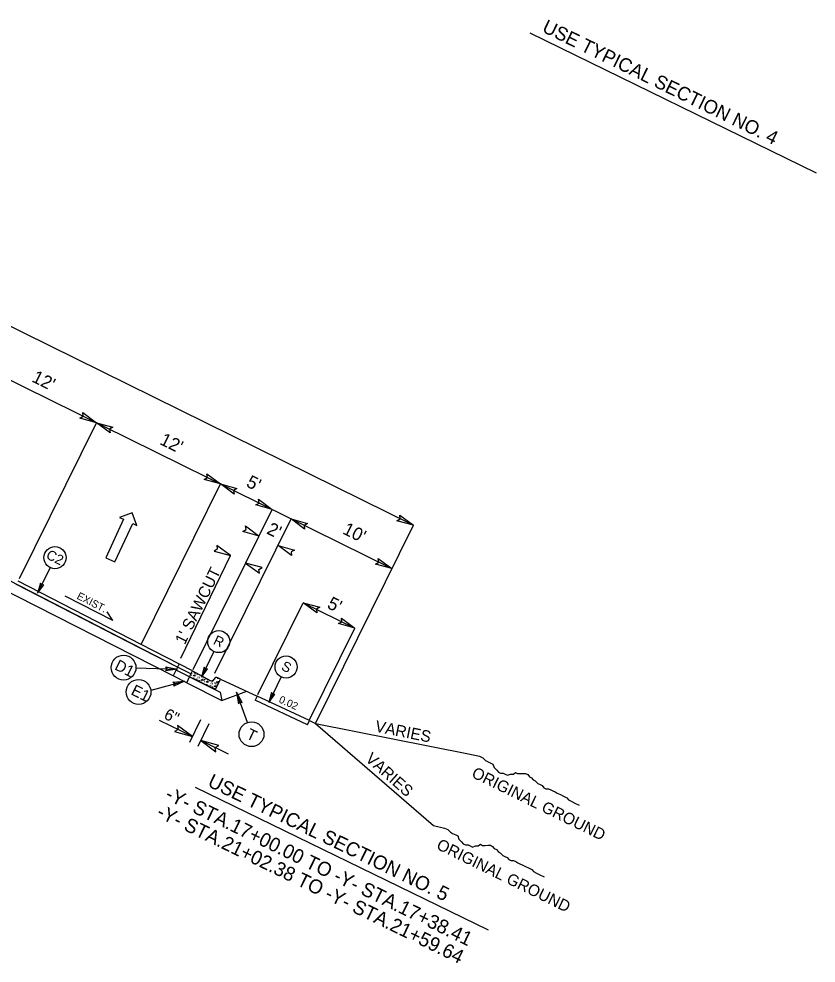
# Model space of a CAD drawing. Extents: x 1518247 to 1523638, y 635234 to 639927.
# Drawn here: x 1522712 to 1523403, y 635313 to 636132 of the extents above; entities that cross this region are included whole.
import ezdxf

# ---------------------------------------------------------------- set-up
doc = ezdxf.new("R2010")
doc.units = 0
for name, color, linetype in [('DTM TIN Hull White', 7, 'Continuous'), ('Prop Dimension', 7, 'Continuous'), ('Prop Lane Arrow CELL', 7, 'Continuous'), ('Prop Shade Light', 7, 'Continuous'), ('Sheet Typical CELL', 7, 'Continuous'), ('Typical Berm CELL', 7, 'Continuous'), ('Typical Berm Information CELL', 7, 'Continuous'), ('Typical Curb CELL', 7, 'Continuous'), ('Typical Hinge Slope Arterial CELL', 7, 'Continuous'), ('Typical Hinge Slope Interstate CELL', 7, 'Continuous'), ('Typical ID Circle CELL', 7, 'Continuous'), ('Typical Pavement Slope CELL', 7, 'Continuous'), ('Typical Pavement Slope Information CELL', 7, 'Continuous'), ('Typical Shoulder Slope CELL', 7, 'Continuous'), ('Typical Text ID Circle CELL', 7, 'Continuous'), ('Typical Text Label CELL', 7, 'Continuous')]:
    doc.layers.add(name, color=color, linetype=linetype)

# ---------------------------------------------------------------- blocks, each defined once
blk = doc.blocks.new('TERMINATOR')
at = {"layer": 'Prop Shade Light'}
blk.add_lwpolyline([(-0.469, 0.081), (0, 0), (-0.471, -0.083), (-0.411, 0)], close=True, dxfattribs=at)

msp = doc.modelspace()

# ---------------------------------------------------------------- linework, layer by layer
at = {"layer": 'DTM TIN Hull White'}
for p, q in [((1522849.5, 635569.87), (1522681, 635656.43)), ((1522845.72, 635562.41), (1522676.71, 635648.08))]:
    msp.add_line(p, q, dxfattribs=at)
at = {"layer": 'Prop Dimension'}
for p, q in [((1522165.11, 636131.96), (1523054.02, 635692.85)), ((1522146.52, 636094.32), (1523035.43, 635655.21)), ((1522712.52, 635646.73), (1522779.23, 635781.77)), ((1522818.32, 635590.03), (1522886.79, 635728.64)), ((1522863.14, 635567.89), (1522931.61, 635706.5)), ((1522881.84, 635564.61), (1522947.93, 635698.41)), ((1522969.34, 635521.41), (1523054.02, 635692.85)), ((1522852.4, 635577.73), (1522895.4, 635666.53)), ((1522919.28, 635546.14), (1522958.58, 635625.69)), ((1522958.58, 635625.69), (1523003.4, 635603.55)), ((1522964.11, 635524), (1523003.4, 635603.55)), ((1522862.49, 635509.62), (1522833.85, 635523.6)), ((1522869.55, 635524.08), (1522860.02, 635504.56)), ((1522876.72, 635520.58), (1522867.19, 635501.06)), ((1522893.66, 635494.4), (1522869.66, 635506.12))]:
    msp.add_line(p, q, dxfattribs=at)
at = {"layer": 'Prop Lane Arrow CELL'}
for p, q in [((1522810.29, 635703.64), (1522799.19, 635699.68)), ((1522799.19, 635699.68), (1522802.76, 635698.02)), ((1522814.19, 635692.71), (1522810.29, 635703.64)), ((1522802.76, 635698.02), (1522787.28, 635664.68)), ((1522795.13, 635661.03), (1522810.62, 635694.37)), ((1522810.62, 635694.37), (1522814.19, 635692.71)), ((1522787.28, 635664.68), (1522795.13, 635661.03))]:
    msp.add_line(p, q, dxfattribs=at)
at = {"layer": 'Prop Shade Light'}
for points in [[(1522730.7, 635642.56), (1522728.18, 635633.91), (1522733.51, 635641.24), (1522731.59, 635640.91)], [(1522839.52, 635570.17), (1522849.42, 635568.05), (1522839.32, 635566.68), (1522840.67, 635568.4)], [(1522872.74, 635569.78), (1522870.22, 635561.14), (1522875.55, 635568.47), (1522873.64, 635568.14)], [(1522845.48, 635556.76), (1522855.57, 635557.64), (1522846.31, 635553.37), (1522847.09, 635555.41)], [(1522905.71, 635539.26), (1522900.75, 635548.09), (1522902.44, 635538.04), (1522903.68, 635539.83)], [(1522931.14, 635547.74), (1522928.62, 635539.09), (1522933.95, 635546.42), (1522932.04, 635546.09)]]:
    msp.add_lwpolyline(points, close=True, dxfattribs=at)
at = {"layer": 'Sheet Typical CELL'}
for p, q in [((1522918.58, 635544.72), (1522916.88, 635541.1)), ((1522963.86, 635523.5), (1522918.58, 635544.72)), ((1522962.16, 635519.88), (1522916.88, 635541.1)), ((1522962.16, 635519.88), (1522963.86, 635523.5))]:
    msp.add_line(p, q, dxfattribs=at)
at = {"layer": 'Typical Berm CELL'}
for p, q in [((1522886.83, 635559.44), (1522918.58, 635544.72)), ((1522963.86, 635523.5), (1522969.16, 635521.05))]:
    msp.add_line(p, q, dxfattribs=at)
at = {"layer": 'Typical Curb CELL'}
for p, q in [((1522859.98, 635561.44), (1522862.54, 635566.68)), ((1522882.44, 635550.45), (1522859.98, 635561.44)), ((1522862.54, 635566.68), (1522877.95, 635558.33)), ((1522863.37, 635562.44), (1522864.68, 635563.14)), ((1522864.49, 635561.97), (1522863.37, 635562.44)), ((1522864.68, 635563.14), (1522864.49, 635561.97)), ((1522886.83, 635559.44), (1522884.49, 635560.58)), ((1522870.03, 635558.62), (1522871.09, 635559.38)), ((1522871.69, 635558.25), (1522870.03, 635558.62)), ((1522871.09, 635559.38), (1522871.69, 635558.25)), ((1522874.6, 635556.95), (1522875.89, 635557.65)), ((1522875.7, 635556.48), (1522874.6, 635556.95)), ((1522875.89, 635557.65), (1522875.7, 635556.48)), ((1522881.24, 635559.39), (1522881.29, 635559.48)), ((1522881.24, 635553.14), (1522882.31, 635553.89)), ((1522882.91, 635552.76), (1522881.24, 635553.14)), ((1522882.31, 635553.89), (1522882.91, 635552.76)), ((1522882.44, 635550.45), (1522886.83, 635559.44)), ((1522883.65, 635557.28), (1522883.4, 635556.39)), ((1522883.4, 635556.39), (1522884.84, 635556.2)), ((1522884.84, 635556.2), (1522883.65, 635557.28))]:
    msp.add_line(p, q, dxfattribs=at)
for centre in [(1522860.2, 635561.65), (1522861.5, 635562.86), (1522861.61, 635564.39), (1522861.99, 635560.52), (1522862.19, 635565.19), (1522862.54, 635564.63), (1522862.56, 635562.85), (1522863.73, 635560.43), (1522864.07, 635565.28), (1522864.56, 635564.09), (1522865.42, 635564.8), (1522866.29, 635562.55), (1522866.48, 635563.59), (1522867.25, 635561.13), (1522868.26, 635562.54), (1522868.5, 635560.83), (1522868.63, 635562.92), (1522870.81, 635561.53), (1522871.67, 635560.55), (1522884.43, 635559.77), (1522865.47, 635559.32), (1522866.88, 635559.59), (1522866.89, 635558.31), (1522868.75, 635558.1), (1522870.12, 635556.99), (1522871.43, 635556.16), (1522872.72, 635557.37), (1522872.83, 635558.9), (1522873.21, 635555.03), (1522873.41, 635559.7), (1522873.76, 635559.15), (1522873.78, 635557.36), (1522874.95, 635554.94), (1522875.1, 635559.41), (1522875.78, 635558.6), (1522876.7, 635553.84), (1522877.51, 635557.06), (1522877.7, 635558.1), (1522878.1, 635554.1), (1522878.11, 635552.83), (1522878.47, 635555.64), (1522879.48, 635557.05), (1522879.72, 635555.34), (1522879.85, 635557.43), (1522879.98, 635552.61), (1522882.03, 635556.05), (1522882.89, 635555.06), (1522884.96, 635557.09), (1522886.22, 635558.51), (1522881.34, 635551.5)]:
    msp.add_circle(centre, 0.0802, dxfattribs=at)
for centre, start, end in [((1522883.44, 635558.43), 63.93772, 153.93772), ((1522879.09, 635560.44), 241.55327, 333.93772)]:
    msp.add_arc(centre, 2.4, start, end, dxfattribs=at)
at = {"layer": 'Typical Hinge Slope Interstate CELL'}
for p, q in [((1522850.89, 635572.75), (1522845.72, 635562.41)), ((1522857.51, 635556.27), (1522859.98, 635561.44)), ((1522860.01, 635561.42), (1522886.64, 635548.19)), ((1522857.51, 635556.27), (1522887.94, 635541)), ((1522886.64, 635548.19), (1522887.94, 635541)), ((1522887.94, 635541), (1522909.57, 635548.9)), ((1522969.16, 635521.05), (1523071.42, 635432.47)), ((1522969.16, 635521.05), (1523101.86, 635494.71))]:
    msp.add_line(p, q, dxfattribs=at)
for points in [[(1523101.86, 635494.71), (1523111.46, 635492.51), (1523114.25, 635491.14), (1523116.58, 635488.85), (1523118.43, 635487.94), (1523121.22, 635486.58), (1523123.08, 635485.67), (1523124.02, 635482.89), (1523126.36, 635480.6), (1523127.76, 635478.76), (1523129.62, 635477.85), (1523131.93, 635477.87), (1523133.79, 635476.96), (1523135.65, 635476.05), (1523138.41, 635477), (1523140.73, 635477.02), (1523142.57, 635478.42), (1523144.43, 635477.51), (1523146.74, 635477.52), (1523149.05, 635477.55), (1523151.36, 635477.57), (1523153.22, 635476.66), (1523154.62, 635474.82), (1523156.48, 635473.91), (1523157.88, 635472.06), (1523159.74, 635471.15), (1523162.07, 635468.86), (1523163.93, 635467.95), (1523165.79, 635467.04), (1523167.19, 635465.2), (1523169.05, 635464.29), (1523171.36, 635464.31), (1523173.22, 635463.4), (1523175.07, 635462.49), (1523176.93, 635461.58), (1523178.79, 635460.67), (1523181.58, 635459.31), (1523184.36, 635457.94), (1523187.15, 635456.58), (1523188.55, 635454.73), (1523191.33, 635453.37), (1523194.12, 635452), (1523197.84, 635450.18)], [(1523071.42, 635432.47), (1523081.01, 635430.26), (1523083.8, 635428.9), (1523086.13, 635426.61), (1523087.99, 635425.7), (1523090.78, 635424.33), (1523092.64, 635423.42), (1523093.58, 635420.65), (1523095.92, 635418.36), (1523097.32, 635416.51), (1523099.18, 635415.6), (1523101.49, 635415.63), (1523103.35, 635414.72), (1523105.2, 635413.81), (1523107.97, 635414.75), (1523110.28, 635414.78), (1523112.13, 635416.18), (1523113.98, 635415.27), (1523116.29, 635415.28), (1523118.61, 635415.3), (1523120.92, 635415.33), (1523122.78, 635414.42), (1523124.18, 635412.57), (1523126.04, 635411.66), (1523127.44, 635409.82), (1523129.3, 635408.91), (1523131.63, 635406.62), (1523133.49, 635405.71), (1523135.35, 635404.8), (1523136.75, 635402.96), (1523138.6, 635402.05), (1523140.92, 635402.07), (1523142.78, 635401.16), (1523144.63, 635400.25), (1523146.49, 635399.34), (1523148.35, 635398.43), (1523151.14, 635397.06), (1523153.92, 635395.7), (1523156.71, 635394.33), (1523158.11, 635392.49), (1523160.89, 635391.13), (1523163.68, 635389.76), (1523167.39, 635387.94)]]:
    msp.add_lwpolyline(points, dxfattribs=at)
at = {"layer": 'Typical ID Circle CELL'}
for p, q in [((1522739.04, 635656.18), (1522728.18, 635633.91)), ((1522881.09, 635583.4), (1522870.22, 635561.14)), ((1522813.47, 635569.23), (1522849.43, 635568.01)), ((1522939.49, 635561.35), (1522928.62, 635539.09)), ((1522826.53, 635549.74), (1522855.59, 635557.61)), ((1522910.07, 635521.84), (1522900.75, 635548.09))]:
    msp.add_line(p, q, dxfattribs=at)
for centre, radius in [((1522743.25, 635664.79), 9.59), ((1522885.29, 635592.01), 9.59), ((1522802.69, 635569.39), 10.78), ((1522943.69, 635569.97), 9.59), ((1522815.7, 635548.3), 10.78), ((1522913.68, 635511.68), 10.78)]:
    msp.add_circle(centre, radius, dxfattribs=at)
at = {"layer": 'Typical Pavement Slope CELL'}
for p, q in [((1522818.08, 635589.54), (1522711.37, 635644.39)), ((1522816.68, 635586.68), (1522709.97, 635641.53)), ((1522849.5, 635569.87), (1522816.68, 635586.68)), ((1522862.54, 635566.68), (1522818.08, 635589.54))]:
    msp.add_line(p, q, dxfattribs=at)
at = {"layer": 'Typical Pavement Slope Information CELL'}
for q in [(1522752, 635631.45), (1522788.5, 635617.83)]:
    msp.add_line((1522793.45, 635610.14), q, dxfattribs=at)
at = {"layer": 'Typical Shoulder Slope CELL'}
for p, q in [((1522861.18, 635563.87), (1522849.5, 635569.87)), ((1522857.51, 635556.27), (1522845.72, 635562.41)), ((1522860.01, 635561.42), (1522848.25, 635567.31))]:
    msp.add_line(p, q, dxfattribs=at)
at = {"layer": 'Typical Text Label CELL'}
for p, q in [((1523155.17, 636119.94), (1523403.3, 635998.36)), ((1522864.85, 635465.6), (1523118.86, 635341.99))]:
    msp.add_line(p, q, dxfattribs=at)

# ---------------------------------------------------------------- block references
at = {"layer": 'Prop Dimension'}
for p, xscale, yscale, rotation in [((1522779.23, 635781.77), 30.9388560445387, 33.305184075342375, -26.28853950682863), ((1522779.23, 635781.77), 30.9388560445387, 33.305184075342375, 153.71146049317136), ((1522886.79, 635728.64), 30.9388560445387, 33.305184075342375, -26.28853950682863), ((1522886.79, 635728.64), 30.9388560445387, 33.305184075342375, 153.71146049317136), ((1522931.61, 635706.5), 30.9388560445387, 33.305184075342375, -26.28853950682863), ((1522947.93, 635698.41), 30.9388560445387, 33.305184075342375, 153.71146049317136), ((1523054.02, 635692.85), 30.9388560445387, 33.305184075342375, -26.28853950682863), ((1522920.34, 635683.45), 30.9388560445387, 33.305184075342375, -26.28853950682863), ((1522895.4, 635666.53), 30.938856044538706, -33.30518407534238, -25.836011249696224), ((1522936.66, 635675.36), 30.9388560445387, 33.305184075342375, 153.71146049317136), ((1522908.58, 635660.09), 30.938856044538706, -33.30518407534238, 154.1639887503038), ((1523035.43, 635655.21), 30.9388560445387, 33.305184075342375, -26.28853950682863), ((1522958.58, 635625.69), 30.9388560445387, 33.305184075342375, 153.71146049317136), ((1523003.4, 635603.55), 30.9388560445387, 33.305184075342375, -26.28853950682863), ((1522862.49, 635509.62), 33.82820784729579, -36.41552511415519, -26.020730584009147), ((1522869.66, 635506.12), 33.82820784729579, -36.41552511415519, 153.97926941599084)]:
    msp.add_blockref('TERMINATOR', p, dxfattribs=dict(at, xscale=xscale, yscale=yscale, rotation=rotation))

# ---------------------------------------------------------------- texts
for s, height, rotation, p in [("12'", 11.189, 333.71146, (1522722.39, 635817.75)), ("12'", 11.189, 333.71146, (1522833.25, 635763.53)), ("5'", 11.189, 333.71146, (1522908.33, 635726.8)), ("2'", 11.189, 333.71146, (1522926.05, 635685.95)), ("10'", 11.189, 333.71146, (1522991.92, 635685.93)), ("1' SAWCUT", 10, 63.93772, (1522855.82, 635588.72)), ("5'", 11.189, 333.71146, (1522978.47, 635621.46)), ('6"', 9.969, 333.97927, (1522836.94, 635525.58))]:
    msp.add_text(s, height=height, rotation=rotation, dxfattribs=at).set_placement(p)
at = {"layer": 'Typical Berm Information CELL'}
msp.add_text('0.02', height=6.491, rotation=335.74614, dxfattribs=at).set_placement((1522936.81, 635539.44))
at = {"layer": 'Typical Hinge Slope Arterial CELL'}
for s, height, rotation, p in [('VARIES', 9.969, 348.67108, (1523020.27, 635514)), ('VARIES', 9.969, 318.31424, (1523011.77, 635489.2)), ('ORIGINAL GROUND', 9.9687, 333.89618, (1523103.77, 635474.79)), ('ORIGINAL GROUND', 9.9687, 333.89618, (1523073.33, 635412.55))]:
    msp.add_text(s, height=height, rotation=rotation, dxfattribs=at).set_placement(p)
at = {"layer": 'Typical Pavement Slope CELL'}
for s, p in [('-Y- STA.17+00.00 TO -Y- STA.17+38.41', (1522837.98, 635455.78)), ('-Y- STA.21+02.38 TO -Y- STA.21+59.64', (1522830.52, 635440.44))]:
    msp.add_text(s, height=12.1642, rotation=334.0511, dxfattribs=at).set_placement(p)
at = {"layer": 'Typical Pavement Slope Information CELL'}
msp.add_text('EXIST.', height=6.476, rotation=332.79198, dxfattribs=at).set_placement((1522761.59, 635629.44))
at = {"layer": 'Typical Text ID Circle CELL'}
for s, height, rotation, p in [('C2', 8.581, 333.97927, (1522734.82, 635664.4)), ('R', 8.58, 333.97927, (1522879.81, 635590.18)), ('D1', 9.65, 333.61889, (1522794.26, 635568.15)), ('S', 8.58, 333.97927, (1522938.76, 635567.87)), ('E1', 9.65, 333.61889, (1522808.45, 635546.47)), ('T', 9.65, 334.53754, (1522908.33, 635508.37))]:
    msp.add_text(s, height=height, rotation=rotation, dxfattribs=at).set_placement(p)
at = {"layer": 'Typical Text Label CELL'}
for s, height, rotation, p in [('USE TYPICAL SECTION NO. 4', 11.8983, 333.89618, (1523164.88, 636121.19)), ('USE TYPICAL SECTION NO. 5', 12.1642, 334.0511, (1522874.78, 635466.91))]:
    msp.add_text(s, height=height, rotation=rotation, dxfattribs=at).set_placement(p)

doc.saveas('drawing.dxf')
